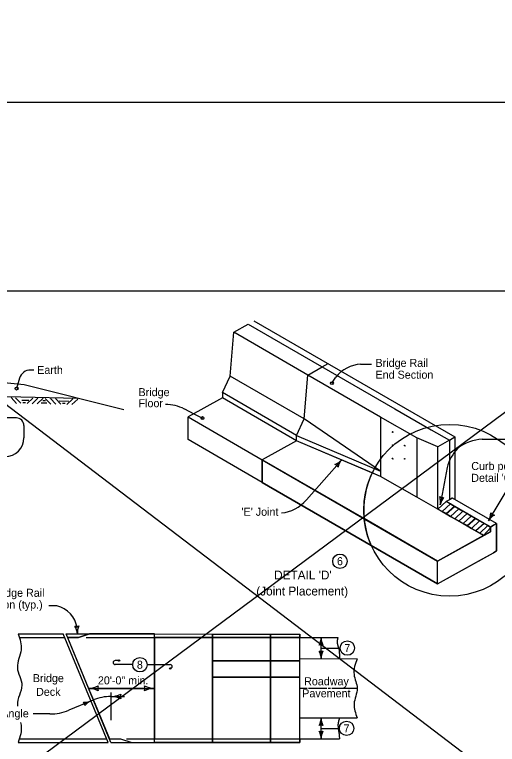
# Model space of a CAD drawing. Extents: x 8925 to 81668, y 4369 to 11918.
# Drawn here: x 18391 to 19595, y 5603 to 7423 of the extents above; entities that cross this region are included whole.
import ezdxf

# ---------------------------------------------------------------- set-up
doc = ezdxf.new("R2010")
doc.units = 0
for name, color, linetype in [('dsnShtPlotShapeBatchPrint', 7, 'Continuous'), ('dsnStdBlock', 7, 'Continuous'), ('dsnStdBlockNotModified', 7, 'Continuous'), ('dsnStdBorder', 7, 'Continuous'), ('Level 3', 7, 'Continuous'), ('Level 5', 7, 'Continuous'), ('SheetBorder', 7, 'Continuous')]:
    doc.layers.add(name, color=color, linetype=linetype)

msp = doc.modelspace()

# ---------------------------------------------------------------- linework, layer by layer
at = {"layer": 'dsnShtPlotShapeBatchPrint'}
for p, q in [((19029.4, 5869.5), (18884.5, 5869.5)), ((18884.5, 5869.5), (18884.5, 5811)), ((19029.4, 5811), (19029.4, 5869.5)), ((19101.9, 5869.5), (19029.4, 5869.5)), ((19029.4, 5869.5), (19029.4, 5811)), ((19101.9, 5811), (19101.9, 5869.5)), ((19029.4, 5811), (18884.5, 5811)), ((18884.5, 5811), (18884.5, 5771)), ((18884.5, 5811), (19029.4, 5811)), ((19029.4, 5771), (19029.4, 5811)), ((19029.4, 5811), (19029.4, 5811)), ((19101.9, 5811), (19029.4, 5811)), ((19029.4, 5811), (19029.4, 5771)), ((19029.4, 5811), (19101.9, 5811)), ((19101.9, 5771), (19101.9, 5811)), ((18884.5, 5771), (18884.5, 5616.7)), ((18884.5, 5771), (19029.4, 5771)), ((19029.4, 5616.7), (19029.4, 5771)), ((19029.4, 5771), (19029.4, 5616.7)), ((19101.9, 5771), (19029.4, 5771)), ((19029.4, 5771), (19101.9, 5771)), ((19101.9, 5616.7), (19101.9, 5771)), ((18884.5, 5616.7), (19029.4, 5616.7)), ((19029.4, 5616.7), (19101.9, 5616.7))]:
    msp.add_line(p, q, dxfattribs=at)
for points in [[(18739.6, 5878.3), (18884.5, 5878.2), (18884.5, 5869.5), (18764.6, 5869.6), (18739.6, 5869.6)], [(19029.4, 5878.2), (19029.4, 5869.5), (18884.5, 5869.5), (18884.5, 5878.2)], [(19101.9, 5878.2), (19101.9, 5869.5), (19029.4, 5869.5), (19029.4, 5878.2)], [(18884.5, 5607.9), (18739.6, 5607.9), (18739.6, 5616.8), (18746.9, 5616.8), (18790.1, 5616.7), (18837.8, 5616.7), (18884.5, 5616.7)], [(18884.5, 5607.9), (18884.5, 5616.7), (19029.4, 5616.7), (19029.4, 5607.8)], [(19101.9, 5607.8), (19029.4, 5607.8), (19029.4, 5616.7), (19101.9, 5616.7)]]:
    msp.add_lwpolyline(points, close=True, dxfattribs=at)
msp.add_lwpolyline([(19029.4, 5771), (19029.4, 5771), (18884.5, 5771)], dxfattribs=at)
at = {"layer": 'dsnStdBlock'}
msp.add_lwpolyline([(17303, 6733.9), (20438, 6733.9), (20438, 4723.9), (17303, 4723.9)], close=True, dxfattribs=at)
at = {"layer": 'dsnStdBlockNotModified'}
msp.add_lwpolyline([(17198.5, 4619.4), (20542.5, 4619.4), (20542.5, 7203.4), (17198.5, 7203.4)], close=True, dxfattribs=at)
at = {"layer": 'dsnStdBorder'}
for p, q in [((18987.5, 6659.5), (19489.2, 6369.8)), ((19158.3, 6544.5), (19172.5, 6552.7)), ((18438.9, 6536.6), (18430.5, 6536.6)), ((19253.9, 6551.4), (19280.7, 6551.4)), ((18403.3, 6516.1), (18395.7, 6490.1)), ((19113, 6414.7), (18928.1, 6521.5)), ((19182.4, 6503.7), (19191.7, 6519)), ((18302.3, 6511.4), (18414.6, 6500.2)), ((18414.6, 6500.2), (18662.8, 6438.1)), ((19094.2, 6373.3), (18909.2, 6480.1)), ((18909.2, 6480.1), (18909.2, 6467.1)), ((18370.4, 6470.3), (18548.2, 6466.7)), ((18382.1, 6467.8), (18395.9, 6453.3)), ((18392.9, 6467.4), (18406.3, 6453.5)), ((18436.2, 6466.6), (18421.7, 6452.7)), ((18448.6, 6466.1), (18434.2, 6452.2)), ((18461.6, 6466), (18447.2, 6452.2)), ((18467, 6465.9), (18480.9, 6451.5)), ((18480, 6465.4), (18493.9, 6451)), ((18492.5, 6465.4), (18506.3, 6451)), ((18535.7, 6464.6), (18521.3, 6450.7)), ((18548.1, 6464.1), (18533.7, 6450.2)), ((18814.6, 6439.4), (18837.9, 6427.6)), ((18837.9, 6427.6), (18859.3, 6416.8)), ((18395.1, 6417.1), (18370.4, 6417.1)), ((19303.5, 6419.3), (19303.5, 6271.4)), ((18414, 6398.1), (18414, 6367.8)), ((19094.2, 6360.3), (19008.3, 6312.7)), ((19094.2, 6360.3), (19008.3, 6312.7)), ((19282.9, 6280.2), (19094.2, 6360.3)), ((19303.5, 6271.4), (19094.2, 6360.3)), ((19394, 6367.1), (19394, 6219.2)), ((19475.1, 6361.6), (19489.2, 6369.8)), ((19489.2, 6369.8), (19489.2, 6213.6)), ((19557.3, 6364.4), (19665.3, 6364.4)), ((19446.8, 6189.6), (19446.8, 6345.3)), ((19008.3, 6312.7), (19008.3, 6256.1)), ((19262.5, 6165.9), (19008.3, 6312.7)), ((19008.3, 6312.7), (19008.3, 6256.1)), ((19008.3, 6312.7), (19262.5, 6165.9)), ((19008.3, 6312.7), (19445.6, 6060.2)), ((19206.9, 6313), (19118.5, 6212.6)), ((19303.5, 6271.4), (19282.9, 6280.2)), ((19469.5, 6293.3), (19452.3, 6200.3)), ((19394, 6219.2), (19303.5, 6271.4)), ((19394, 6219.2), (19303.5, 6271.4)), ((19008.3, 6256.1), (19445.6, 6003.6)), ((19008.3, 6256.1), (19280.3, 6099)), ((19445.6, 6003.6), (19008.3, 6256.1)), ((19572.7, 6160.4), (19628.8, 6252.8)), ((19446.8, 6189.6), (19394, 6219.2)), ((19446.8, 6189.6), (19394, 6219.2)), ((19467.2, 6208.6), (19446.8, 6189.6)), ((19467.2, 6208.6), (19446.8, 6189.6)), ((19475.1, 6212.9), (19467.2, 6208.6)), ((19477.7, 6202.5), (19467.2, 6208.6)), ((19467.2, 6208.6), (19477.7, 6202.5)), ((19577.4, 6144.9), (19467.2, 6208.6)), ((19593.1, 6153.6), (19482.9, 6217.3)), ((19593.1, 6153.6), (19482.9, 6217.3)), ((19457.2, 6183.6), (19446.8, 6189.6)), ((19446.8, 6189.6), (19457.2, 6183.6)), ((19560.6, 6123.9), (19446.8, 6189.6)), ((19457.2, 6183.6), (19477.7, 6202.5)), ((19477.7, 6202.5), (19457.2, 6183.6)), ((19477.7, 6202.5), (19457.2, 6183.6)), ((19467.6, 6177.6), (19488.1, 6196.5)), ((19488.1, 6196.5), (19467.6, 6177.6)), ((19488.1, 6196.5), (19467.6, 6177.6)), ((19488.1, 6196.5), (19477.7, 6202.5)), ((19477.7, 6202.5), (19488.1, 6196.5)), ((19478, 6171.6), (19498.5, 6190.5)), ((19498.5, 6190.5), (19478, 6171.6)), ((19498.5, 6190.5), (19478, 6171.6)), ((19498.5, 6190.5), (19488.1, 6196.5)), ((19488.1, 6196.5), (19498.5, 6190.5)), ((19508.9, 6184.5), (19498.5, 6190.5)), ((19498.5, 6190.5), (19508.9, 6184.5)), ((19457.2, 6183.6), (19467.6, 6177.6)), ((19467.6, 6177.6), (19478, 6171.6)), ((19478, 6171.6), (19488.4, 6165.6)), ((19488.4, 6165.6), (19508.9, 6184.5)), ((19508.9, 6184.5), (19488.4, 6165.6)), ((19508.9, 6184.5), (19488.4, 6165.6)), ((19519.2, 6178.6), (19499.1, 6160)), ((19509.2, 6153.6), (19529.7, 6172.5)), ((19529.7, 6172.5), (19509.2, 6153.6)), ((19529.7, 6172.5), (19509.2, 6153.6)), ((19540.1, 6166.5), (19529.7, 6172.5)), ((19529.7, 6172.5), (19540.1, 6166.5)), ((19262.5, 6165.9), (19445.6, 6060.2)), ((19445.6, 6060.2), (19262.5, 6165.9)), ((19488.4, 6165.6), (19509.2, 6153.6)), ((19509.2, 6153.6), (19519.7, 6147.6)), ((19519.7, 6147.6), (19540.1, 6166.5)), ((19540.1, 6166.5), (19519.7, 6147.6)), ((19540.1, 6166.5), (19519.7, 6147.6)), ((19550.6, 6160.4), (19530.2, 6141.5)), ((19561.6, 6154.1), (19541.2, 6135.2)), ((19593.1, 6153.6), (19585.3, 6149.3)), ((19585.3, 6149.3), (19593.1, 6153.6)), ((19593.1, 6153.6), (19585.3, 6149.3)), ((19593.1, 6085.4), (19593.1, 6153.6)), ((19519.7, 6147.6), (19530.2, 6141.5)), ((19530.2, 6141.5), (19550.9, 6129.5)), ((19550.9, 6129.5), (19571.3, 6148.5)), ((19571.3, 6148.5), (19550.9, 6129.5)), ((19571.3, 6148.5), (19550.9, 6129.5)), ((19560.6, 6123.9), (19577.4, 6143)), ((19577.4, 6143), (19560.6, 6123.9)), ((19560.6, 6123.9), (19577.4, 6143)), ((19577.4, 6144.9), (19571.3, 6148.5)), ((19571.3, 6148.5), (19577.4, 6144.9)), ((19585.3, 6149.3), (19577.4, 6144.9)), ((19577.4, 6144.9), (19585.3, 6149.3)), ((19585.3, 6149.3), (19577.4, 6144.9)), ((19577.4, 6143), (19577.4, 6144.9)), ((19577.4, 6133.3), (19577.4, 6144.9)), ((19577.4, 6133.3), (19577.4, 6143)), ((19445.6, 6060.2), (19577.4, 6133.3)), ((19445.6, 6060.2), (19560.6, 6123.9)), ((19560.6, 6123.9), (19445.6, 6060.2)), ((19550.9, 6129.5), (19557, 6126)), ((19560.6, 6123.9), (19557, 6126)), ((19557, 6126), (19560.6, 6123.9)), ((19577.4, 6133.3), (19560.6, 6123.9)), ((19560.6, 6123.9), (19577.4, 6133.3)), ((19280.3, 6099), (19445.6, 6003.6)), ((19550, 6061.5), (19585.3, 6081)), ((19570.2, 6072.7), (19585.3, 6081)), ((19585.3, 6081), (19593.1, 6085.4)), ((19593.1, 6085.4), (19585.3, 6081)), ((19445.6, 6003.6), (19570.2, 6072.7)), ((19445.6, 6003.6), (19445.6, 6060.2)), ((18496, 5948.4), (18476.5, 5948.4)), ((18400, 5878.3), (18512.1, 5878.3)), ((18402.9, 5869.6), (18515.8, 5869.6)), ((18624.3, 5607.9), (18512.3, 5878.3)), ((18630.9, 5607.9), (18519, 5878.3)), ((18519, 5878.3), (18739.6, 5878.3)), ((18522.5, 5869.6), (18550, 5869.6)), ((18550, 5869.6), (18577.7, 5878.3)), ((18569.6, 5869.6), (19197.2, 5869.5)), ((18739.6, 5816.8), (18739.6, 5878.3)), ((18739.6, 5616.8), (18739.6, 5878.3)), ((18739.6, 5878.3), (19101.9, 5878.2)), ((18884.5, 5869.5), (18739.6, 5869.6)), ((18884.5, 5607.9), (18884.5, 5878.2)), ((19029.4, 5607.8), (19029.4, 5878.2)), ((19101.9, 5607.8), (19101.9, 5878.2)), ((19101.9, 5616.8), (19101.9, 5869.6)), ((19155.3, 5816.8), (19155.3, 5869.5)), ((19155.3, 5843.2), (19184.7, 5843.2)), ((19184.7, 5843.2), (19202.7, 5843.2)), ((18651.4, 5811.9), (18641.5, 5811.9)), ((19101.9, 5816.8), (19245.2, 5816.7)), ((18685.4, 5802.1), (18641.5, 5802.1)), ((18721.4, 5802.1), (18779, 5802.1)), ((18575, 5742.7), (18739.6, 5742.7)), ((18716, 5742.7), (18598.6, 5742.7)), ((18598.6, 5742.7), (18716, 5742.7)), ((18739.6, 5742.7), (18739.6, 5742.7)), ((18739.6, 5742.7), (18739.6, 5674.8)), ((18630.9, 5732.4), (18630.9, 5663.7)), ((18630.9, 5722.4), (18664.9, 5722.4)), ((18587.1, 5713.6), (18525.8, 5688.2)), ((18478.7, 5678.9), (18437.3, 5678.9)), ((18739.6, 5674.8), (18739.6, 5616.8)), ((18739.6, 5607.9), (18739.6, 5674.8)), ((19101.9, 5669.3), (19245.2, 5669.3)), ((19155.3, 5616.7), (19155.3, 5669.3)), ((19155.3, 5643), (19184.7, 5643)), ((19184.7, 5643), (19200.9, 5643)), ((18400, 5607.9), (18624.3, 5607.9)), ((18402.7, 5616.8), (18620.6, 5616.8)), ((18627.3, 5616.8), (18654.8, 5616.8)), ((18627.3, 5616.8), (18654.8, 5616.8)), ((18630.9, 5607.9), (18739.6, 5607.9)), ((18654.8, 5616.8), (18683, 5607.9)), ((18654.8, 5616.8), (18683, 5607.9)), ((18670, 5616.8), (19200.9, 5616.7)), ((18683, 5607.9), (18739.6, 5607.9)), ((18739.6, 5616.8), (18790.1, 5616.7)), ((18739.6, 5607.9), (19101.9, 5607.8)), ((18790.1, 5616.7), (18790.1, 5616.7))]:
    msp.add_line(p, q, dxfattribs=at)
for points in [[(18973.3, 6651.3), (19339.3, 6440), (19429.8, 6387.8), (19475.1, 6361.6), (19446.8, 6345.3), (19394, 6367.1), (19303.5, 6419.3), (19122.5, 6523.8), (18937.5, 6630.6)], [(18937.5, 6630.6), (18973.3, 6651.3)], [(18909.2, 6480.1), (18928.1, 6521.5), (18937.5, 6630.6)], [(19122.5, 6523.8), (19158.3, 6544.5)], [(19094.2, 6360.3), (19094.2, 6373.3), (19113, 6414.7), (19122.5, 6523.8)], [(18408.4, 6461.6), (18426.5, 6461.3)], [(18909.2, 6467.1), (18823.3, 6419.5)], [(19094.2, 6360.3), (18909.2, 6467.1)], [(18411.1, 6455.8), (18417.6, 6455.7)], [(18457, 6454.8), (18471.2, 6454.5)], [(18460.9, 6460.6), (18467.5, 6460.4)], [(18501.9, 6459.8), (18526, 6459.3)], [(18510.6, 6453.8), (18517.1, 6453.7)], [(18823.3, 6419.5), (19008.3, 6312.7)], [(18823.3, 6362.9), (18823.3, 6419.5)], [(19094.2, 6373.3), (19303.5, 6284.5), (19113, 6414.7)], [(19008.3, 6256.1), (18823.3, 6362.9)], [(19094.2, 6360.3), (19008.3, 6312.7)], [(19475.1, 6361.6), (19475.1, 6212.9)], [(19008.3, 6256.1), (19008.3, 6312.7)], [(19475.1, 6212.9), (19467.2, 6208.6)], [(19482.9, 6217.3), (19482.2, 6216.8), (19475.1, 6212.9)], [(19482.9, 6217.3), (19475.1, 6212.9)], [(19478, 6171.6), (19467.6, 6177.6), (19457.2, 6183.6)], [(19509.2, 6153.6), (19488.4, 6165.6), (19478, 6171.6)], [(19529.7, 6172.5), (19519.2, 6178.6), (19508.9, 6184.5)], [(19508.9, 6184.5), (19519.2, 6178.6), (19529.7, 6172.5)], [(19557, 6126), (19550.9, 6129.5), (19530.2, 6141.5), (19519.7, 6147.6), (19509.2, 6153.6)], [(19571.3, 6148.5), (19561.6, 6154.1), (19540.1, 6166.5)], [(19540.1, 6166.5), (19561.6, 6154.1), (19571.3, 6148.5)], [(19593.1, 6153.6), (19593.1, 6085.4)], [(19577.4, 6144.9), (19577.4, 6143), (19577.4, 6133.3)], [(19445.6, 6003.6), (19550, 6061.5), (19570.2, 6072.7)], [(18738.9, 5742.7), (18739.6, 5742.7), (18739.6, 5878.3), (18577.7, 5878.3), (18550, 5869.6), (18522.6, 5869.6), (18575.1, 5742.7), (18575.7, 5742.7)], [(18739.6, 5869.6), (18739.6, 5802.1), (18739.6, 5742.7)], [(18884.5, 5616.7), (18884.5, 5743.2), (18884.5, 5869.5)], [(18575.1, 5742.7), (18587.2, 5713.6), (18627.3, 5616.8)], [(18739.6, 5607.9), (18739.6, 5616.8), (18739.6, 5669.3), (18739.6, 5742.7)], [(18739.6, 5742.7), (18739.6, 5742.7)], [(19101.9, 5743.1), (19120.6, 5743.1)], [(19123.7, 5743.1), (19169.7, 5743.1)], [(19172.8, 5743.1), (19179, 5743.1)], [(19182, 5743.1), (19245.2, 5743.1)], [(18790.1, 5616.7), (18837.8, 5616.7), (18884.5, 5616.7)]]:
    msp.add_lwpolyline(points, dxfattribs=at)
for centre, radius in [((19475.7, 6186.9), 214.2), ((19202.3, 6059.6), 18), ((19220.7, 5843.2), 18), ((18703.4, 5801.6), 18), ((19218.9, 5643), 18)]:
    msp.add_circle(centre, radius, dxfattribs=at)
for centre, radius, start, end in [((18430.5, 6508.2), 28.4, 90, 163.739), ((19261.6, 6460.7), 91, 94.8409, 140.1467), ((18766.9, 6344.8), 105.9, 63.2177, 90), ((18395.1, 6398.1), 18.9, 0, 90), ((18366.7, 6367.8), 47.3, 270, 360), ((19566.2, 6247.3), 117.5, 94.3399, 126.627), ((19582.8, 6262.3), 117.5, 137.5971, 164.7195), ((19475.7, 6186.9), 214.2, 154.1687, 185.6063), ((19475.7, 6186.9), 214.2, 154.1687, 185.6063), ((19048.6, 6271), 91, 274.8409, 320.1467), ((19475.7, 6186.9), 214.2, 185.6063, 204.2018), ((19475.7, 6186.9), 214.2, 185.6063, 204.2018), ((18480.9, 5883.4), 66.7, 8.4828, 76.8823), ((19115.1, 5869.5), 40.2, 331.9275, 360), ((19195.4, 5869.5), 40.2, 180, 208.0725), ((19155.3, 5835.9), 15.5, 72.2666, 107.7334), ((19155.3, 5850.5), 15.5, 252.2666, 287.7333), ((19115.1, 5816.8), 40.2, 360, 28.0725), ((19195.4, 5816.8), 40.2, 151.9275, 180), ((18641.5, 5807), 4.92, 90, 270), ((18779, 5797.2), 4.92, 270, 90), ((18575, 5795), 52.2, 270, 298.0725), ((18575, 5690.5), 52.2, 61.9275, 90), ((18575, 5690.5), 52.2, 61.9275, 89.8364), ((18575, 5795), 52.2, 270.8433, 298.0725), ((18618.7, 5742.7), 20.2, 162.2666, 197.7334), ((18618.7, 5742.7), 20.2, 162.2667, 179.9839), ((18618.7, 5742.7), 20.2, 179.9839, 197.7334), ((18695.8, 5742.7), 20.2, 342.2666, 17.7334), ((18739.6, 5795), 52.2, 241.9275, 270), ((18695.8, 5742.7), 20.2, 0.0161, 17.7334), ((18739.6, 5795), 52.2, 241.9275, 269.1567), ((18739.6, 5690.5), 52.2, 90.0176, 118.0725), ((18695.8, 5742.7), 20.2, 342.2666, 0.0161), ((18739.6, 5690.5), 52.2, 90, 118.0725), ((18739.6, 5795), 52.2, 269.9824, 270), ((18630.9, 5607.9), 114.5, 90, 112.5), ((18630.9, 5774.6), 52.2, 270, 298.0725), ((18630.9, 5774.6), 52.2, 270, 298.0725), ((18630.9, 5670.1), 52.2, 61.9275, 90), ((18630.9, 5670.1), 52.2, 61.9275, 90), ((18674.7, 5722.4), 20.2, 162.2666, 197.7334), ((18674.7, 5722.4), 20.2, 162.2666, 197.7334), ((18566.1, 5748.4), 40.2, 264.4275, 292.5), ((18550.3, 5698.4), 15.5, 4.7666, 40.2333), ((18596.8, 5674.2), 40.2, 112.5, 140.5725), ((18478.7, 5801.7), 122.9, 270, 292.5), ((19115.1, 5669.3), 40.2, 331.9275, 360), ((19195.4, 5669.3), 40.2, 180, 208.0725), ((19155.3, 5635.6), 15.5, 72.2666, 107.7334), ((19155.3, 5650.4), 15.5, 252.2666, 287.7333), ((19115.1, 5616.7), 40.2, 360, 28.0725), ((19195.4, 5616.7), 40.2, 151.9275, 180), ((18749.9, 5616.7), 40.2, 359.9859, 360)]:
    msp.add_arc(centre, radius, start, end, dxfattribs=at)
for centre in [(19333.7, 6382.2), (19333.7, 6349), (19363.8, 6348.2), (19333.7, 6315.8), (19363.8, 6315)]:
    msp.add_ellipse(centre, major_axis=(0.67, -1.15), ratio=0.57735, dxfattribs=at)
for points in [[(18400, 5878.3), (18406.9, 5839.1), (18397.6, 5794.7), (18408.9, 5750.3), (18397.6, 5700.8), (18397.9, 5698.4)], [(19245.2, 5816.7), (19237.4, 5777.1), (19245.2, 5743), (19237.4, 5703.8), (19245.2, 5669.3)], [(18405.7, 5657.5), (18406.9, 5651.3), (18400, 5607.9)]]:
    msp.add_spline(points, degree=3, dxfattribs=at)
for points in [[(19197.2, 5869.5), (19197.1, 5869), (19196.9, 5868.6), (19196.7, 5868.1), (19196.6, 5867.6), (19196.4, 5867.1), (19196.3, 5866.6), (19196.1, 5865.6), (19195.8, 5864.6), (19195.7, 5863.6), (19195.5, 5862.6), (19195.4, 5861.6), (19195.3, 5860.6), (19195.3, 5860.1), (19195.3, 5859.6), (19195.3, 5859.1), (19195.3, 5858.6), (19195.3, 5858.1), (19195.3, 5857.6), (19195.4, 5856.7), (19195.5, 5855.7), (19195.6, 5854.8), (19195.8, 5853.8), (19196, 5852.9), (19196.2, 5852), (19196.8, 5850.1), (19197.4, 5848.2), (19197.9, 5846.3), (19198.5, 5844.4), (19199, 5842.6), (19199.6, 5840.7), (19199.8, 5839.7), (19200, 5838.8), (19200.2, 5837.8), (19200.3, 5836.8), (19200.4, 5835.9), (19200.5, 5834.9), (19200.6, 5833.4), (19200.6, 5831.9), (19200.7, 5830.4), (19200.8, 5828.9), (19200.9, 5827.4), (19201, 5825.9), (19201, 5824.3), (19201.1, 5822.8), (19201.2, 5821.3), (19201.2, 5819.8), (19201.3, 5818.3), (19201.3, 5816.8)], [(19201.3, 5669.3), (19201, 5668.4), (19200.7, 5667.6), (19200.4, 5666.7), (19200.1, 5665.8), (19199.9, 5664.9), (19199.6, 5664), (19199.1, 5662.3), (19198.6, 5660.5), (19198.3, 5658.8), (19197.7, 5656.1), (19197.4, 5653.5), (19197.3, 5650.8), (19197.3, 5650.4), (19197.3, 5649.9), (19197.3, 5649.5), (19197.3, 5649), (19197.4, 5648.6), (19197.4, 5648.1), (19197.4, 5647.2), (19197.5, 5646.2), (19197.6, 5645.2), (19197.7, 5644.2), (19197.8, 5643.2), (19198, 5642.2), (19198.3, 5640.2), (19198.6, 5638.3), (19198.9, 5636.3), (19199.3, 5634.3), (19199.6, 5632.3), (19199.9, 5630.4), (19200, 5629.4), (19200.1, 5628.4), (19200.2, 5627.4), (19200.3, 5626.4), (19200.4, 5625.4), (19200.5, 5624.4), (19200.6, 5621.8), (19200.8, 5619.3), (19200.9, 5616.7)]]:
    msp.add_open_spline(points, degree=3, dxfattribs=at)
at = {"layer": 'Level 3'}
for centre in [(18651.4, 5811.9), (18779, 5792.3)]:
    msp.add_circle(centre, 1.78, dxfattribs=at)
for centre, radius, start, end in [((19175, 6341), 42.5, 290.5435, 318.616), ((19183.3, 6286.2), 16.4, 30.8827, 66.3494), ((19238.8, 6284.9), 42.5, 138.616, 166.6885), ((19458.8, 6235.3), 16.4, 241.782, 277.2487), ((19410.5, 6208), 42.5, 349.5153, 17.5878), ((19494.1, 6192.5), 42.5, 141.4428, 169.5153), ((19536.3, 6182.5), 42.5, 328.7108, 356.7833), ((19609, 6138.3), 42.5, 120.6383, 148.7108), ((19591.2, 6190.9), 16.4, 220.9775, 256.4442), ((18544.7, 5913.8), 16.4, 256.6331, 292.0998), ((18505, 5875), 42.5, 4.3665, 32.439), ((18589.8, 5881.5), 42.5, 156.294, 184.3665)]:
    msp.add_arc(centre, radius, start, end, dxfattribs=at)
at = {"layer": 'Level 5'}
for centre in [(19182.4, 6503.7), (18395.7, 6490.1), (18859.3, 6416.8)]:
    msp.add_circle(centre, 3.54, dxfattribs=at)
at = {"layer": 'SheetBorder'}
for p, q in [((17092.5, 7422.9), (21027.2, 4427.1)), ((20872.2, 7364.8), (17082.8, 4553.2))]:
    msp.add_line(p, q, dxfattribs=at)

# ---------------------------------------------------------------- texts
at = {"layer": 'dsnShtPlotShapeBatchPrint'}
for s, height, p in [('Earth', 20, (18447.1, 6526.7)), ('6', 20, (19194.8, 6049.8)), ('(Joint Placement)', 22, (18993.6, 5974.3)), ('7', 20, (19213.1, 5833.2)), ('8', 20, (18695.8, 5791.6)), ('Bridge', 20, (18436.3, 5758.2)), ('20\'-0" min.', 20, (18598.5, 5752.6)), ('Roadway', 20, (19112.9, 5750.4)), ('Deck', 20, (18444.3, 5724)), ('Pavement', 20, (19108.2, 5720.4)), ('Skew Angle', 20, (18284.8, 5670.3)), ('7', 20, (19211.3, 5633))]:
    msp.add_text(s, height=height, dxfattribs=at).set_placement(p)
at = {"layer": 'dsnStdBorder'}
for s, height, p in [('Bridge Rail ', 20, (19291, 6544.4)), ('End Section', 20, (19291, 6514.9)), ('Bridge', 20, (18699.9, 6471.4)), ('Floor', 20, (18699.9, 6443.8)), ('Curb per', 20, (19529.8, 6287.2)), ("Detail 'G'", 20, (19529.8, 6257.7)), ("'E' Joint", 20, (18956.8, 6173)), ("DETAIL 'D'", 22, (19038, 6014.3)), ('Bridge Rail', 20, (18334.5, 5971)), ('End Section (typ.)', 20, (18248.1, 5941.6))]:
    msp.add_text(s, height=height, dxfattribs=at).set_placement(p)

doc.saveas('drawing.dxf')
